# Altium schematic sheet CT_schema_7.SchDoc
size 278 x 170 mm
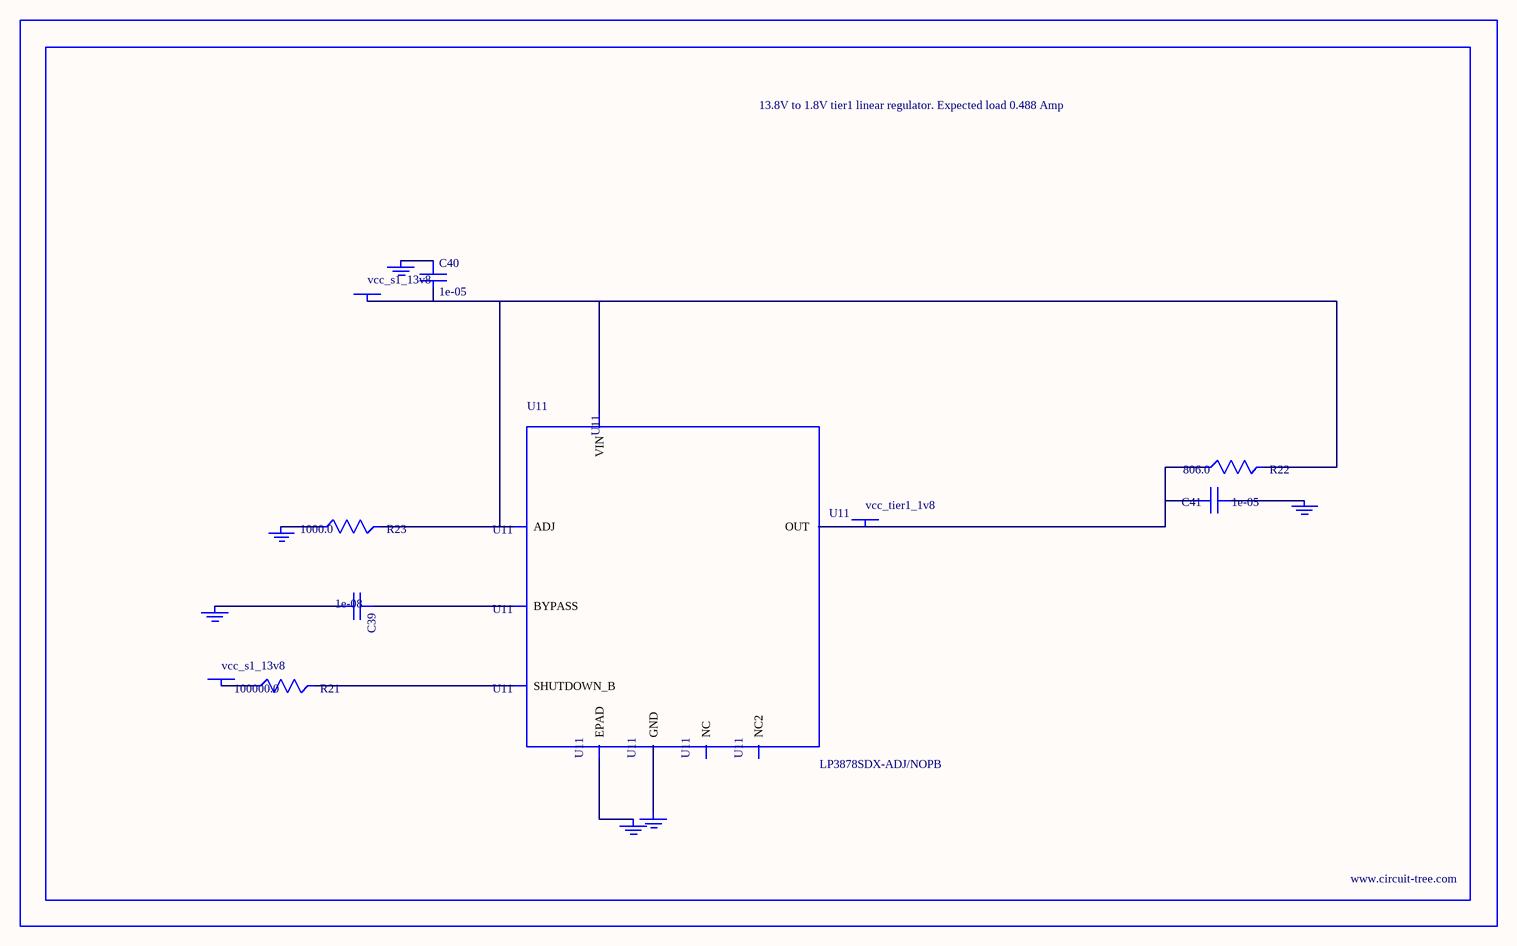
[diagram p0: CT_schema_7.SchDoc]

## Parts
BORDER6  (no value)
C39  1e-08  [C0402]
C40  1e-05  [C1210]
C41  1e-05  [C0805]
GND_INSTANCE_6_0  (no value)
GND_INSTANCE_6_1  (no value)
GND_INSTANCE_6_2  (no value)
GND_INSTANCE_6_3  (no value)
GND_INSTANCE_6_4  (no value)
GND_INSTANCE_6_5  (no value)
POWER_INSTANCE_6_0  vcc_s1_13v8
POWER_INSTANCE_6_1  vcc_s1_13v8
POWER_INSTANCE_6_2  vcc_tier1_1v8
R21  100000.0  [R0603]
R22  806.0  [R0603]
R23  1000.0  [R0603]
U11  LP3878SDX-ADJ/NOPB  [WSON-8]

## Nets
NetC39_1: C39.1 U11.1(BYPASS)
NetC39_2: C39.2 GND_INSTANCE_6_0.0(GND)
NetC40_1: C40.1 GND_INSTANCE_6_1.0(GND)
NetC40_2: C40.2 POWER_INSTANCE_6_0.0(PWR) R22.2 R23.2 U11.4(VIN) U11.6(ADJ)
NetC41_1: C41.1 GND_INSTANCE_6_2.0(GND)
NetC41_2: C41.2 POWER_INSTANCE_6_2.0(PWR) R22.1 U11.5(OUT)
NetGND_INSTANCE_6_3_0: GND_INSTANCE_6_3.0(GND) R23.1
NetGND_INSTANCE_6_4_0: GND_INSTANCE_6_4.0(GND) U11.PAD(EPAD)
NetGND_INSTANCE_6_5_0: GND_INSTANCE_6_5.0(GND) U11.3(GND)
NetPOWER_INSTANCE_6_1_0: POWER_INSTANCE_6_1.0(PWR) R21.1
NetR21_2: R21.2 U11.8(SHUTDOWN_B)

Not connected (* = marked no-connect by the designer): U11 2(NC) 7(NC2)

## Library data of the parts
BORDER6 = BORDER_PAGE6
C39 = C0402C103K3RAC
C40 = C1210C106K5PACTU
C41 = GRM219R60J106ME19D
GND_INSTANCE_6_0-GND_INSTANCE_6_5 = GND
POWER_INSTANCE_6_0-POWER_INSTANCE_6_2 = PWR
R21 = RC0603JR-07100KL
R22 = ERJ-3EKF8060V
R23 = RC0603JR-071KL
